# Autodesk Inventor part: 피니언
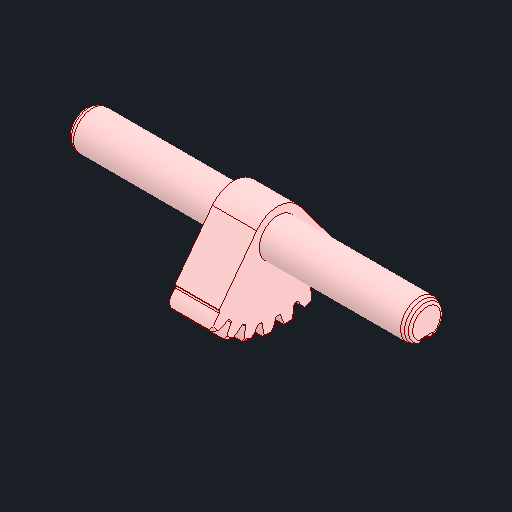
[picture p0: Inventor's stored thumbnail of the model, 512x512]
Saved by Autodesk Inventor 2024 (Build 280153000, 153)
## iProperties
Created: 2024-05
Part Number: 피니언
Material: 강철, 탄소
Document SubType Name: Modeling
Designer: kh_501
Density: 7.85 g/cm^3
Appearance: 기본값
Author: jhkim
Sending System: Autodesk Inventor 2025
Preprocessor: ST-DEVELOPER v20
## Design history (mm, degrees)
feature "솔리드1"
node "솔리드2"
